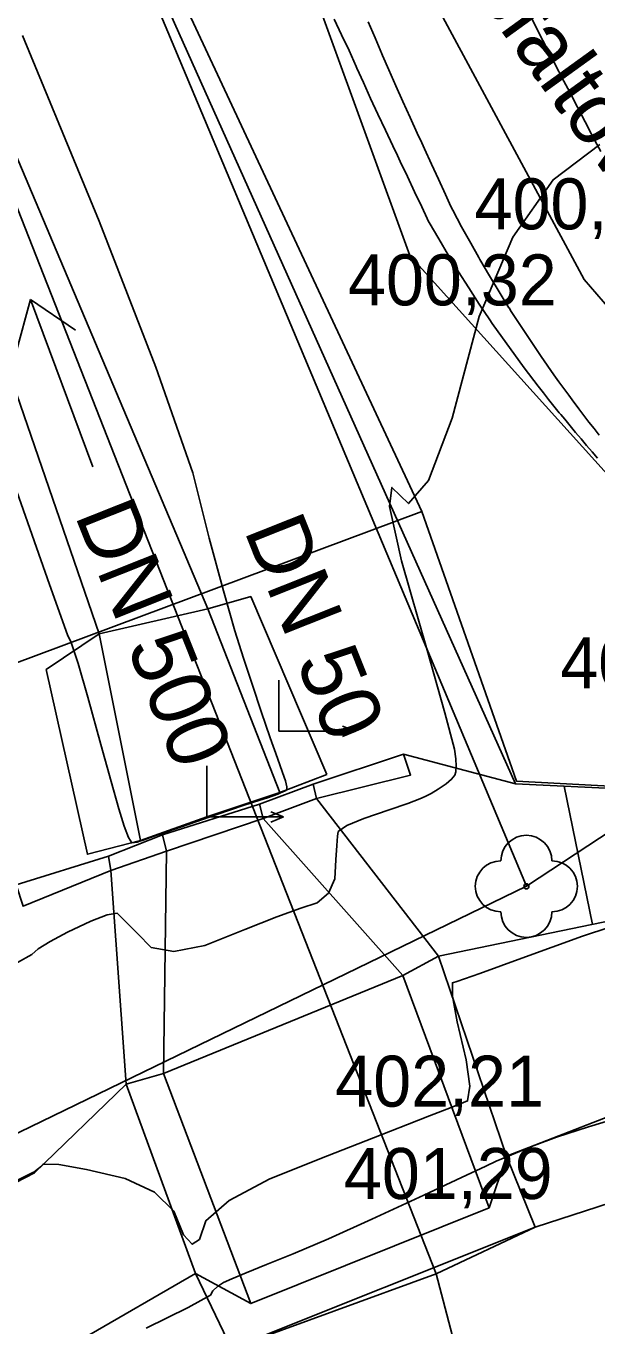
# Model space of a CAD drawing. Extents: x -574342 to -508101, y -1143544 to -1123894.
# Drawn here: x -508422.34 to -508411.16, y -1143333.68 to -1143308.19 of the extents above; entities that cross this region are included whole.
import ezdxf

# ---------------------------------------------------------------- set-up
doc = ezdxf.new("R2010")
doc.units = 0
for name, color, linetype in [('01_PARCELY_NAVRH_PC', 7, 'Continuous'), ('01_PARCELY_NAVRH_VHO', 7, 'Continuous'), ('01_PARCELY_NAVRH_ŽP', 7, 'Continuous'), ('05_VHO_V_NÁDRŽ_STAV', 7, 'Continuous'), ('05_VHO_V_TOK_STAV', 7, 'Continuous'), ('1000', 7, 'Continuous'), ('15', 7, 'Continuous'), ('21', 7, 'Continuous'), ('37', 7, 'Continuous'), ('43', 7, 'Continuous'), ('51', 7, 'Continuous'), ('52', 7, 'Continuous'), ('54', 7, 'Continuous'), ('55', 7, 'Continuous'), ('57', 7, 'Continuous'), ('60', 7, 'Continuous'), ('61', 7, 'Continuous'), ('Level 255', 7, 'Continuous'), ('VRST HL', 7, 'Continuous'), ('VRST VEDL', 7, 'Continuous')]:
    doc.layers.add(name, color=color, linetype=linetype)

msp = doc.modelspace()

# ---------------------------------------------------------------- linework, layer by layer
at = {"layer": '01_PARCELY_NAVRH_PC'}
msp.add_lwpolyline([(-508451.57, -1143168.14), (-508437.66, -1143207.58), (-508425.52, -1143241.92), (-508422.7, -1143249.88), (-508420.08, -1143265.35), (-508416.18, -1143288.91), (-508414.34, -1143296.2), (-508410.3, -1143304.94), (-508406.96, -1143310.33), (-508402.64, -1143313.55), (-508394.5, -1143317.14), (-508397.53, -1143325.93), (-508402.47, -1143323.55), (-508407.39, -1143320.93), (-508414.82, -1143312.69), (-508418.17, -1143303.49), (-508422.28, -1143289.33), (-508426.41, -1143265.09), (-508431, -1143245.85), (-508431.86, -1143242.81), (-508432.73, -1143240.34), (-508445.99, -1143206.42), (-508454.33, -1143183.49)], dxfattribs=at)
at = {"layer": '01_PARCELY_NAVRH_VHO'}
for points in [[(-508469.74, -1143257.73), (-508446.21, -1143255.76), (-508446.02, -1143260.22), (-508445.4, -1143275.01), (-508441.9, -1143297.61), (-508434.31, -1143320.59), (-508432.21, -1143324.29), (-508414.59, -1143317.71), (-508420.1, -1143305.91), (-508426.78, -1143287.77), (-508433.97, -1143265.8), (-508436.6, -1143259.34), (-508438.17, -1143255.47), (-508441.16, -1143248.09), (-508442.91, -1143245.61), (-508437.61, -1143243.22), (-508434.06, -1143242.54), (-508431.86, -1143242.81), (-508432.73, -1143240.34), (-508433.72, -1143240.11), (-508438.05, -1143241.09), (-508444.11, -1143244.2), (-508446.56, -1143243.12), (-508452.58, -1143244.39)], [(-508425.23, -1143400.39), (-508448.26, -1143343.08), (-508432.21, -1143324.29), (-508414.59, -1143317.71), (-508412.73, -1143323), (-508402.47, -1143323.55), (-508397.53, -1143325.93), (-508388.37, -1143325.84), (-508380.92, -1143326.77), (-508370.86, -1143331.67), (-508363.15, -1143337.53), (-508357.56, -1143346.15), (-508348.55, -1143381.54), (-508344.81, -1143391.35), (-508336.31, -1143410.38)]]:
    msp.add_lwpolyline(points, dxfattribs=at)
at = {"layer": '01_PARCELY_NAVRH_ŽP'}
msp.add_lwpolyline([(-508436.6, -1143259.34), (-508429.75, -1143260.04), (-508426.41, -1143265.09), (-508422.28, -1143289.33), (-508418.17, -1143303.49), (-508414.82, -1143312.69), (-508407.39, -1143320.93), (-508402.47, -1143323.55), (-508412.73, -1143323), (-508414.59, -1143317.71), (-508420.1, -1143305.91), (-508426.78, -1143287.77), (-508433.97, -1143265.8)], close=True, dxfattribs=at)
at = {"layer": '05_VHO_V_NÁDRŽ_STAV'}
msp.add_lwpolyline([(-508407.31, -1143425.12), (-508421.04, -1143398.5), (-508435.23, -1143353.37), (-508436.55, -1143347.52), (-508434.17, -1143342.98), (-508418.32, -1143334.12), (-508414.306, -1143332.655), (-508412.37, -1143331.74), (-508405, -1143329.35), (-508396.85, -1143328.19), (-508388.18, -1143328.1), (-508381.94, -1143328.58), (-508371.85, -1143333.32), (-508365.54, -1143338.18), (-508362.9, -1143341.9), (-508360.75, -1143347.81), (-508357.9, -1143373.51), (-508353.94, -1143387.64), (-508340.54, -1143421.17)], dxfattribs=at)
at = {"layer": '05_VHO_V_TOK_STAV'}
msp.add_lwpolyline([(-508396.743, -1143399.678), (-508414.306, -1143332.655), (-508430.208, -1143292.193), (-508438.98, -1143265.17), (-508442.91, -1143250.47), (-508445.36, -1143246.6), (-508447.49, -1143245.57), (-508453.89, -1143245.84)], dxfattribs=at)
at = {"layer": '1000'}
for points in [[(-508416.308, -1143308.057), (-508416.161, -1143308.366), (-508416.014, -1143308.675), (-508415.875, -1143308.988), (-508415.86, -1143309.021), (-508415.733, -1143309.3), (-508415.591, -1143309.612), (-508415.447, -1143309.923), (-508415.301, -1143310.233), (-508415.155, -1143310.543), (-508415.064, -1143310.732), (-508415.01, -1143310.847), (-508414.87, -1143311.144), (-508414.731, -1143311.441), (-508414.591, -1143311.738), (-508414.483, -1143311.969), (-508414.481, -1143311.973), (-508414.442, -1143312.042), (-508414.255, -1143312.368), (-508414.064, -1143312.692), (-508413.892, -1143312.975), (-508413.868, -1143313.012), (-508413.668, -1143313.329), (-508413.464, -1143313.643), (-508413.257, -1143313.951), (-508413.255, -1143313.955), (-508413.208, -1143314.023), (-508412.581, -1143314.897), (-508412.309, -1143315.254), (-508412.206, -1143315.385), (-508412.103, -1143315.516), (-508411.999, -1143315.646), (-508411.894, -1143315.776), (-508411.864, -1143315.812), (-508411.788, -1143315.904), (-508411.682, -1143316.033), (-508411.575, -1143316.16), (-508411.468, -1143316.288), (-508411.36, -1143316.414), (-508411.252, -1143316.54), (-508411.143, -1143316.666)], [(-508415.638, -1143308.114), (-508415.505, -1143308.427), (-508415.37, -1143308.74), (-508415.356, -1143308.773), (-508415.234, -1143309.052), (-508415.097, -1143309.364), (-508414.958, -1143309.675), (-508414.818, -1143309.986), (-508414.677, -1143310.296), (-508414.59, -1143310.485), (-508414.537, -1143310.601), (-508414.4, -1143310.9), (-508414.263, -1143311.198), (-508414.127, -1143311.497), (-508414.02, -1143311.729), (-508414.019, -1143311.732), (-508413.982, -1143311.802), (-508413.809, -1143312.127), (-508413.631, -1143312.45), (-508413.471, -1143312.734), (-508413.45, -1143312.771), (-508413.264, -1143313.089), (-508413.074, -1143313.405), (-508412.881, -1143313.715), (-508412.879, -1143313.718), (-508412.836, -1143313.787), (-508412.252, -1143314.672), (-508411.999, -1143315.034), (-508411.904, -1143315.168), (-508411.807, -1143315.301), (-508411.71, -1143315.433), (-508411.612, -1143315.565), (-508411.585, -1143315.602), (-508411.513, -1143315.697), (-508411.414, -1143315.828), (-508411.314, -1143315.958), (-508411.213, -1143316.087), (-508411.111, -1143316.217)]]:
    msp.add_lwpolyline(points, dxfattribs=at)
at = {"layer": '21'}
msp.add_lwpolyline([(-508412.44, -1143308.031), (-508412.293, -1143308.324), (-508412.144, -1143308.616), (-508411.994, -1143308.908), (-508411.901, -1143309.086), (-508411.842, -1143309.199), (-508411.691, -1143309.49), (-508411.54, -1143309.781), (-508411.388, -1143310.072), (-508411.271, -1143310.298), (-508411.269, -1143310.301), (-508411.237, -1143310.363), (-508411.082, -1143310.652)], dxfattribs=at)
at = {"layer": '37'}
msp.add_lwpolyline([(-508408.82, -1143311.83), (-508404.37, -1143317.04), (-508398.21, -1143321.18), (-508393.66, -1143322.44), (-508393.79, -1143324.58), (-508400.56, -1143323.11), (-508406.32, -1143319.06), (-508411.41, -1143313.16), (-508415.31, -1143305.9), (-508419.33, -1143292.88), (-508424.96, -1143264.72), (-508428.49, -1143248.11), (-508430.27, -1143242.09), (-508442.28, -1143211.48), (-508455.59, -1143171.17), (-508460.82, -1143160.05), (-508470.5, -1143142.85)], dxfattribs=at)
msp.add_lwpolyline([(-508408.82, -1143311.83), (-508404.37, -1143317.04), (-508398.21, -1143321.18), (-508393.66, -1143322.44), (-508393.79, -1143324.58), (-508400.56, -1143323.11), (-508406.32, -1143319.06), (-508411.41, -1143313.16), (-508415.31, -1143305.9), (-508419.33, -1143292.88), (-508424.96, -1143264.72), (-508428.49, -1143248.11), (-508430.27, -1143242.09), (-508442.28, -1143211.48), (-508455.59, -1143171.17), (-508460.82, -1143160.05), (-508470.5, -1143142.85)], dxfattribs=at)
at = {"layer": '43'}
for p, q in [((-508422.537, -1143314.588), (-508422.258, -1143313.557)), ((-508421.037, -1143316.838), (-508422.258, -1143313.557)), ((-508422.258, -1143313.557), (-508421.373, -1143314.155))]:
    msp.add_line(p, q, dxfattribs=at)
at = {"layer": '51'}
for points in [[(-508420.91, -1143320.11), (-508425.97, -1143305.4), (-508432.32, -1143288.39), (-508438.93, -1143266.96), (-508438.98, -1143265.17), (-508437.64, -1143266.69), (-508431.24, -1143288.3), (-508424.98, -1143304.96), (-508418.78, -1143319.62)], [(-508420.91, -1143320.11), (-508425.97, -1143305.4), (-508432.32, -1143288.39), (-508438.93, -1143266.96), (-508438.98, -1143265.17), (-508437.64, -1143266.69), (-508431.24, -1143288.3), (-508424.98, -1143304.96), (-508418.78, -1143319.62)], [(-508340.68, -1143425.01), (-508340.54, -1143421.17), (-508353.94, -1143387.64), (-508357.9, -1143373.51), (-508360.75, -1143347.81), (-508362.9, -1143341.9), (-508365.54, -1143338.18), (-508371.85, -1143333.32), (-508381.94, -1143328.58), (-508388.18, -1143328.1), (-508396.85, -1143328.19), (-508405, -1143329.35), (-508412.37, -1143331.74)], [(-508340.68, -1143425.01), (-508340.54, -1143421.17), (-508353.94, -1143387.64), (-508357.9, -1143373.51), (-508360.75, -1143347.81), (-508362.9, -1143341.9), (-508365.54, -1143338.18), (-508371.85, -1143333.32), (-508381.94, -1143328.58), (-508388.18, -1143328.1), (-508396.85, -1143328.19), (-508405, -1143329.35), (-508412.37, -1143331.74)]]:
    msp.add_lwpolyline(points, dxfattribs=at)
at = {"layer": '52'}
for p, q in [((-508417.39, -1143321.02), (-508417.39, -1143322.02)), ((-508417.39, -1143322.02), (-508415.89, -1143322.02)), ((-508415.89, -1143322.02), (-508416.14, -1143321.92)), ((-508415.89, -1143322.02), (-508416.14, -1143322.12)), ((-508418.8, -1143322.7), (-508418.8, -1143323.7)), ((-508418.8, -1143323.7), (-508417.3, -1143323.7)), ((-508417.3, -1143323.7), (-508417.55, -1143323.6)), ((-508417.3, -1143323.7), (-508417.55, -1143323.8))]:
    msp.add_line(p, q, dxfattribs=at)
at = {"layer": '54'}
msp.add_circle((-508412.54, -1143325.06), 0.05, dxfattribs=at)
for centre, start, end in [((-508412.54, -1143324.56), 0, 180), ((-508413.04, -1143325.06), 90, 270), ((-508412.04, -1143325.06), 270, 90), ((-508412.54, -1143325.56), 180, 0)]:
    msp.add_arc(centre, 0.5, start, end, dxfattribs=at)
at = {"layer": '55'}
msp.add_line((-508446.12, -1143341.35), (-508412.54, -1143325.06), dxfattribs=at)
msp.add_line((-508446.12, -1143341.35), (-508412.54, -1143325.06), dxfattribs=at)
msp.add_lwpolyline([(-508408, -1143322.07), (-508412.54, -1143325.06), (-508424.05, -1143297.62), (-508436.1, -1143264.37)], dxfattribs=at)
msp.add_lwpolyline([(-508408, -1143322.07), (-508412.54, -1143325.06), (-508424.05, -1143297.62), (-508436.1, -1143264.37)], dxfattribs=at)
at = {"layer": '57'}
for points in [[(-508416.45, -1143322.87), (-508417.94, -1143319.38), (-508418.78, -1143319.62)], [(-508416.45, -1143322.87), (-508417.94, -1143319.38), (-508418.78, -1143319.62)], [(-508420.91, -1143320.11), (-508418.78, -1143319.62), (-508417.37, -1143323.22)], [(-508420.91, -1143320.11), (-508418.78, -1143319.62), (-508417.37, -1143323.22)], [(-508416.45, -1143322.87), (-508417.37, -1143323.22), (-508418.8, -1143323.7), (-508420.1, -1143324.16), (-508421.14, -1143324.43), (-508421.95, -1143320.81), (-508420.91, -1143320.11), (-508420.1, -1143324.16)], [(-508416.45, -1143322.87), (-508417.37, -1143323.22), (-508418.8, -1143323.7), (-508420.1, -1143324.16), (-508421.14, -1143324.43), (-508421.95, -1143320.81), (-508420.91, -1143320.11), (-508420.1, -1143324.16)], [(-508416.65, -1143323.34), (-508414.26, -1143326.43), (-508412.93, -1143330.35), (-508412.37, -1143331.74), (-508418.32, -1143334.12), (-508419.02, -1143332.65), (-508417.94, -1143333.24), (-508413.27, -1143331.36), (-508412.93, -1143330.35)], [(-508416.65, -1143323.34), (-508414.26, -1143326.43), (-508412.93, -1143330.35), (-508412.37, -1143331.74), (-508418.32, -1143334.12), (-508419.02, -1143332.65), (-508417.94, -1143333.24), (-508413.27, -1143331.36), (-508412.93, -1143330.35)], [(-508413.27, -1143331.36), (-508414.96, -1143326.81), (-508417.7, -1143323.73)], [(-508413.27, -1143331.36), (-508414.96, -1143326.81), (-508417.7, -1143323.73)], [(-508419.59, -1143324.37), (-508419.65, -1143328.73), (-508417.94, -1143333.24)], [(-508419.59, -1143324.37), (-508419.65, -1143328.73), (-508417.94, -1143333.24)], [(-508419.02, -1143332.65), (-508420.38, -1143328.94), (-508420.68, -1143324.75)], [(-508419.02, -1143332.65), (-508420.38, -1143328.94), (-508420.68, -1143324.75)], [(-508420.38, -1143328.94), (-508419.65, -1143328.73), (-508414.96, -1143326.81), (-508414.26, -1143326.43)], [(-508420.38, -1143328.94), (-508419.65, -1143328.73), (-508414.96, -1143326.81), (-508414.26, -1143326.43)]]:
    msp.add_lwpolyline(points, dxfattribs=at)
for points in [[(-508416.72, -1143323.06), (-508414.95, -1143322.47), (-508414.81, -1143322.88), (-508416.65, -1143323.34)], [(-508416.72, -1143323.06), (-508414.95, -1143322.47), (-508414.81, -1143322.88), (-508416.65, -1143323.34)], [(-508417.77, -1143323.45), (-508416.72, -1143323.06), (-508416.65, -1143323.34), (-508417.7, -1143323.73)], [(-508417.77, -1143323.45), (-508416.72, -1143323.06), (-508416.65, -1143323.34), (-508417.7, -1143323.73)], [(-508419.67, -1143324.05), (-508417.77, -1143323.45), (-508417.7, -1143323.73), (-508419.59, -1143324.37)], [(-508419.67, -1143324.05), (-508417.77, -1143323.45), (-508417.7, -1143323.73), (-508419.59, -1143324.37)], [(-508420.73, -1143324.47), (-508419.67, -1143324.05), (-508419.59, -1143324.37), (-508420.68, -1143324.75)], [(-508420.73, -1143324.47), (-508419.67, -1143324.05), (-508419.59, -1143324.37), (-508420.68, -1143324.75)], [(-508422.54, -1143325.03), (-508422.4, -1143325.45), (-508420.68, -1143324.75), (-508420.73, -1143324.47)], [(-508422.54, -1143325.03), (-508422.4, -1143325.45), (-508420.68, -1143324.75), (-508420.73, -1143324.47)]]:
    msp.add_lwpolyline(points, close=True, dxfattribs=at)
at = {"layer": '60'}
for p, q in [((-508412.75, -1143323.05), (-508414.95, -1143322.47)), ((-508412.75, -1143323.05), (-508414.95, -1143322.47)), ((-508402.11, -1143323.57), (-508412.75, -1143323.05)), ((-508402.11, -1143323.57), (-508412.75, -1143323.05))]:
    msp.add_line(p, q, dxfattribs=at)
for points in [[(-508445.13, -1143265.32), (-508440.54, -1143262.92), (-508437.86, -1143263.12), (-508434.77, -1143265.51), (-508427.96, -1143286.38), (-508421.22, -1143304.15), (-508412.75, -1143323.05)], [(-508445.13, -1143265.32), (-508440.54, -1143262.92), (-508437.86, -1143263.12), (-508434.77, -1143265.51), (-508427.96, -1143286.38), (-508421.22, -1143304.15), (-508412.75, -1143323.05)], [(-508414.26, -1143326.43), (-508407.24, -1143324.98), (-508402.11, -1143323.57)], [(-508414.26, -1143326.43), (-508407.24, -1143324.98), (-508402.11, -1143323.57)], [(-508412.93, -1143330.35), (-508406.52, -1143327.86), (-508397.53, -1143325.93), (-508388.37, -1143325.84)], [(-508412.93, -1143330.35), (-508406.52, -1143327.86), (-508397.53, -1143325.93), (-508388.37, -1143325.84)], [(-508448.26, -1143343.08), (-508432.97, -1143336.26), (-508422.18, -1143330.68), (-508420.38, -1143328.94)], [(-508448.26, -1143343.08), (-508432.97, -1143336.26), (-508422.18, -1143330.68), (-508420.38, -1143328.94)], [(-508419.02, -1143332.65), (-508421.24, -1143333.93), (-508436.57, -1143341.85), (-508437.56, -1143344.93), (-508438.58, -1143347.48), (-508436.88, -1143353.76), (-508431.04, -1143370.87)], [(-508419.02, -1143332.65), (-508421.24, -1143333.93), (-508436.57, -1143341.85), (-508437.56, -1143344.93), (-508438.58, -1143347.48), (-508436.88, -1143353.76), (-508431.04, -1143370.87)]]:
    msp.add_lwpolyline(points, dxfattribs=at)
at = {"layer": '61'}
msp.add_line((-508411.242, -1143325.807), (-508411.802, -1143323.097), dxfattribs=at)
msp.add_line((-508411.242, -1143325.807), (-508411.802, -1143323.097), dxfattribs=at)
at = {"layer": 'VRST HL'}
msp.add_lwpolyline([(-508422.514, -1143326.556), (-508422.23, -1143326.398), (-508422.105, -1143326.287), (-508421.871, -1143326.141), (-508421.528, -1143325.959), (-508421.076, -1143325.742), (-508420.754, -1143325.617), (-508420.56, -1143325.585), (-508420.496, -1143325.646), (-508420.363, -1143325.779), (-508420.161, -1143325.983), (-508419.891, -1143326.258), (-508419.45, -1143326.337), (-508418.838, -1143326.219), (-508418.057, -1143325.905), (-508417.429, -1143325.661), (-508416.957, -1143325.487), (-508416.638, -1143325.384), (-508416.418, -1143325.192), (-508416.295, -1143324.91), (-508416.271, -1143324.54), (-508416.252, -1143324.262), (-508416.238, -1143324.078), (-508416.229, -1143323.987), (-508416.057, -1143323.87), (-508415.724, -1143323.728), (-508415.227, -1143323.56), (-508414.861, -1143323.433), (-508414.626, -1143323.347), (-508414.522, -1143323.302), (-508414.402, -1143323.238), (-508414.265, -1143323.154), (-508414.113, -1143323.052), (-508414.004, -1143322.962), (-508413.94, -1143322.882), (-508413.919, -1143322.815), (-508413.914, -1143322.707), (-508413.925, -1143322.559), (-508413.95, -1143322.371), (-508414.136, -1143321.661), (-508414.482, -1143320.43), (-508414.989, -1143318.677), (-508415.219, -1143317.613), (-508415.173, -1143317.24), (-508414.85, -1143317.555), (-508414.458, -1143317.102), (-508413.995, -1143315.88), (-508413.462, -1143313.889), (-508412.803, -1143312.331), (-508412.016, -1143311.206), (-508411.103, -1143310.514)], dxfattribs=at)
at = {"layer": 'VRST VEDL'}
for points in [[(-508422.521, -1143317.317), (-508421.885, -1143319.144), (-508421.531, -1143320.131), (-508421.458, -1143320.28), (-508421.325, -1143320.688), (-508421.133, -1143321.354), (-508420.881, -1143322.278), (-508420.678, -1143323.007), (-508420.525, -1143323.541), (-508420.422, -1143323.879), (-508420.337, -1143324.102), (-508420.27, -1143324.21), (-508420.221, -1143324.203), (-508420.168, -1143324.191), (-508420.112, -1143324.174), (-508420.051, -1143324.153), (-508419.78, -1143324.059), (-508419.297, -1143323.893), (-508418.602, -1143323.653), (-508418.09, -1143323.478), (-508417.761, -1143323.368), (-508417.614, -1143323.322), (-508417.498, -1143323.283), (-508417.412, -1143323.252), (-508417.357, -1143323.228), (-508417.309, -1143323.206), (-508417.268, -1143323.187), (-508417.234, -1143323.171), (-508417.231, -1143323.106), (-508417.259, -1143322.992), (-508417.319, -1143322.829), (-508417.418, -1143322.549), (-508417.557, -1143322.151), (-508417.734, -1143321.635), (-508417.909, -1143321.114), (-508418.083, -1143320.586), (-508418.254, -1143320.053), (-508418.477, -1143319.269), (-508418.752, -1143318.235), (-508419.077, -1143316.951), (-508419.797, -1143314.881), (-508420.909, -1143312.022), (-508422.415, -1143308.377)], [(-508410.35, -1143325.677), (-508411.439, -1143326.035), (-508412.628, -1143326.468), (-508413.45, -1143326.766), (-508413.904, -1143326.927), (-508413.989, -1143326.951), (-508413.987, -1143327.215), (-508413.896, -1143327.719), (-508413.717, -1143328.462), (-508413.649, -1143328.978), (-508413.692, -1143329.266), (-508413.847, -1143329.328), (-508414.095, -1143329.426), (-508414.437, -1143329.559), (-508414.872, -1143329.728), (-508415.538, -1143329.991), (-508416.436, -1143330.347), (-508417.566, -1143330.797), (-508418.361, -1143331.22), (-508418.82, -1143331.615), (-508418.944, -1143331.984), (-508419.09, -1143332.076), (-508419.258, -1143331.89), (-508419.448, -1143331.427), (-508419.829, -1143331.059), (-508420.4, -1143330.786), (-508421.161, -1143330.609), (-508421.698, -1143330.516), (-508422.009, -1143330.507), (-508422.095, -1143330.583), (-508422.157, -1143330.636), (-508422.194, -1143330.665), (-508422.208, -1143330.67), (-508423.34, -1143331.223)], [(-508410.545, -1143329.543), (-508411.319, -1143329.772), (-508411.951, -1143329.979), (-508412.44, -1143330.164), (-508412.834, -1143330.321), (-508413.132, -1143330.447), (-508413.334, -1143330.545), (-508413.808, -1143330.767), (-508414.552, -1143331.115), (-508415.568, -1143331.587), (-508416.419, -1143331.971), (-508417.106, -1143332.267), (-508417.629, -1143332.475), (-508418.031, -1143332.638), (-508418.312, -1143332.756), (-508418.472, -1143332.83), (-508418.595, -1143332.908), (-508418.681, -1143332.989), (-508418.729, -1143333.074), (-508419.165, -1143333.319), (-508419.989, -1143333.725)]]:
    msp.add_lwpolyline(points, dxfattribs=at)

# ---------------------------------------------------------------- texts
at = {"layer": '15'}
for s, rotation, p in [('asfaltová cesta', 305.8449, (-508414.093, -1143306.831)), ('asfaltová cesta', 305.8449, (-508414.093, -1143306.831)), ('DN 500', 291.6928, (-508421.397, -1143317.779)), ('DN 500', 291.6928, (-508421.397, -1143317.779)), ('DN 50', 291.6928, (-508418.079, -1143318.077)), ('DN 50', 291.6928, (-508418.079, -1143318.077))]:
    msp.add_text(s, height=1.2, rotation=rotation, dxfattribs=at).set_placement(p)
at = {"layer": 'Level 255'}
for s, p in [('400,31', (-508413.555, -1143312.18)), ('400,32', (-508416.035, -1143313.67)), ('401,09', (-508411.875, -1143321.18)), ('402,21', (-508416.285, -1143329.38)), ('401,29', (-508416.115, -1143331.19))]:
    msp.add_text(s, height=1, dxfattribs=at).set_placement(p)

doc.saveas('drawing.dxf')
